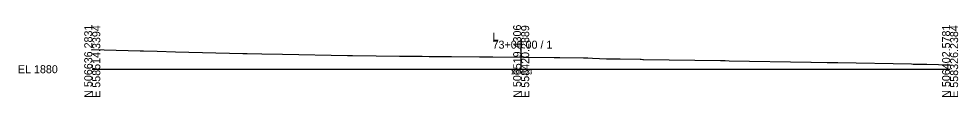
# Model space of a CAD drawing. Extents: x -26 to 4603, y -10 to 4703.
# Drawn here: x 2974.3 to 3302.8, y 1255.3 to 1280.4 of the extents above; entities that cross this region are included whole.
import ezdxf

# ---------------------------------------------------------------- set-up
doc = ezdxf.new("R2010")
doc.units = 0
for name, color, linetype in [('Default', 7, 'Continuous'), ('Exist Cross Section Cell', 7, 'Continuous'), ('Exist XS Ground Line', 7, 'Continuous'), ('Prop XS SS Elevation Text', 7, 'Continuous')]:
    doc.layers.add(name, color=color, linetype=linetype)

msp = doc.modelspace()

# ---------------------------------------------------------------- linework, layer by layer
at = {"layer": 'Exist Cross Section Cell'}
for p, q in [((3150, 1265), (3150, 1275)), ((3000, 1265), (3150, 1265)), ((3150, 1265), (3300, 1265))]:
    msp.add_line(p, q, dxfattribs=at)
at = {"layer": 'Exist XS Ground Line'}
msp.add_lwpolyline([(3000, 1271.87), (3016.76, 1271.41), (3017.95, 1271.38), (3022.65, 1271.27), (3029.1, 1271.09), (3052.64, 1270.52), (3054.16, 1270.49), (3059.29, 1270.4), (3066.52, 1270.26), (3089.28, 1269.83), (3090.97, 1269.81), (3099.27, 1269.71), (3107.46, 1269.6), (3115.41, 1269.51), (3117.83, 1269.49), (3120.35, 1269.49), (3121.98, 1269.49), (3123.41, 1269.49), (3125.63, 1269.5), (3135.48, 1269.34), (3137.97, 1269.32), (3140.04, 1269.31), (3161.57, 1269.13), (3163.54, 1269.09), (3171.85, 1269.04), (3173.3, 1268.95), (3174.9, 1268.85), (3179.83, 1268.69), (3184.64, 1268.62), (3191.58, 1268.47), (3191.92, 1268.46), (3191.94, 1268.46), (3192.49, 1268.45), (3192.74, 1268.44), (3219.73, 1268.03), (3221.31, 1268), (3222.77, 1267.97), (3251.33, 1267.49), (3251.4, 1267.49), (3257.03, 1267.39), (3257.16, 1267.39), (3260.71, 1267.32), (3286.48, 1266.83), (3287.03, 1266.82), (3287.11, 1266.82), (3291.91, 1266.73), (3300, 1266.55)], dxfattribs=at)

# ---------------------------------------------------------------- texts
at = {"layer": 'Default'}
msp.add_text('-', height=0.0001, dxfattribs=at).set_placement((3000, 1265))
at = {"layer": 'Exist Cross Section Cell'}
for s, p in [('N 506636.2831', (3000, 1255)), ('E 558514.3394', (3002.8, 1255)), ('N 506519.4306', (3150, 1255)), ('E 558420.2889', (3152.8, 1255)), ('N 506402.5781', (3300, 1255)), ('E 558326.2384', (3302.8, 1255))]:
    msp.add_text(s, height=2.8, rotation=90, dxfattribs=at).set_placement(p)
for s, p in [('73+00.00 / 1', (3140, 1272.2)), ('L', (3140, 1275)), ('EL 1880', (2974, 1263.6))]:
    msp.add_text(s, height=2.8, dxfattribs=at).set_placement(p)
at = {"layer": 'Prop XS SS Elevation Text'}
msp.add_text('1884.23', height=1.5, dxfattribs=at).set_placement((3146.4, 1263.25))

doc.saveas('drawing.dxf')
